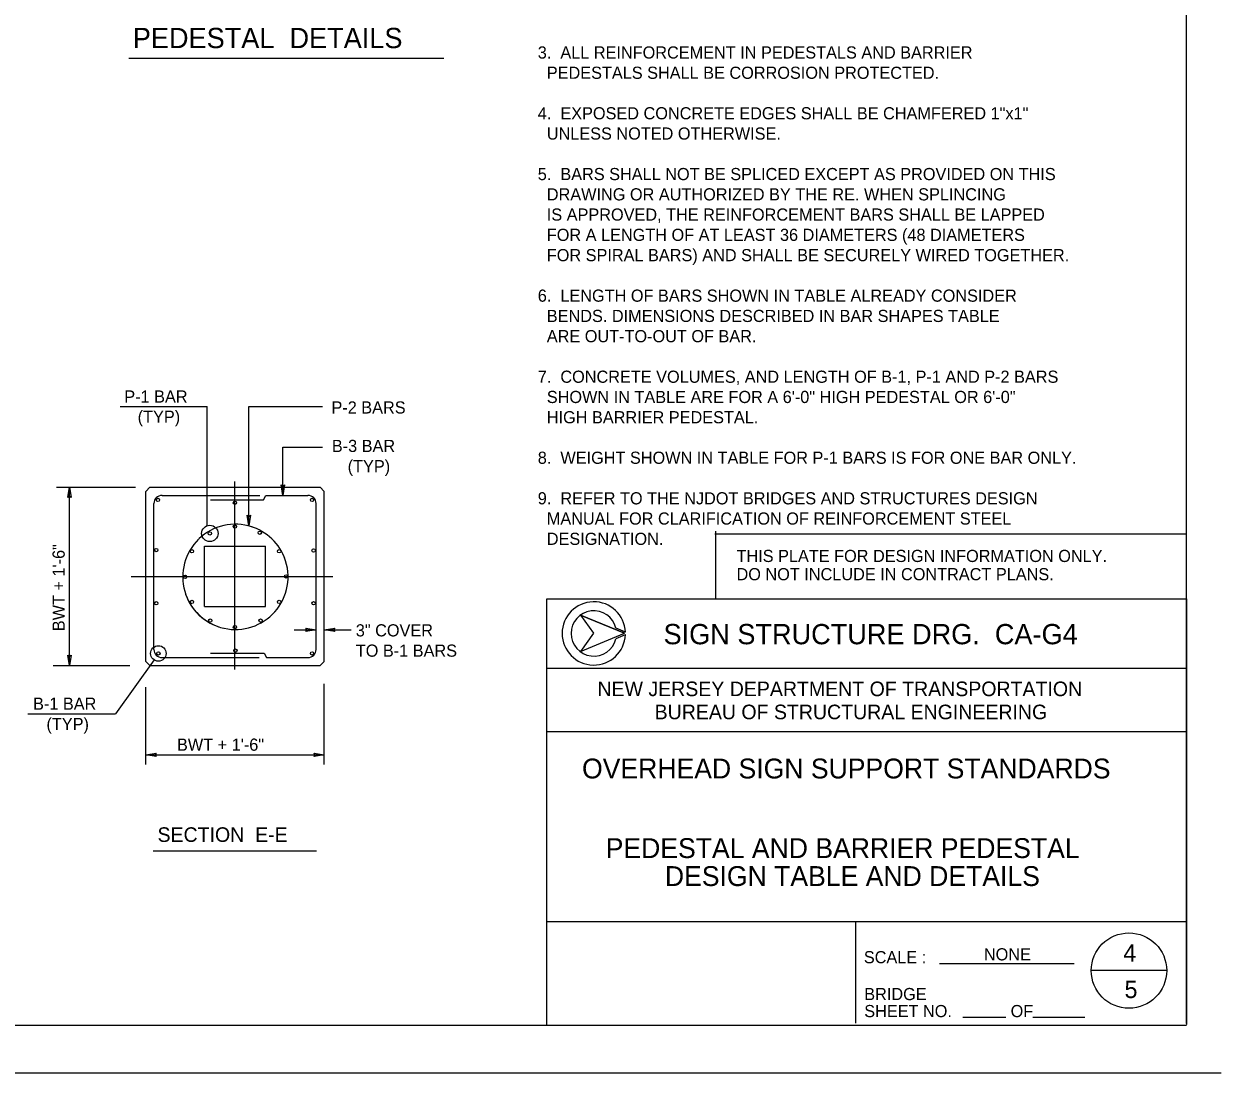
# Model space of a CAD drawing. Extents: x -3 to 26050223, y 0 to 12035012.
# Drawn here: x 44.29 to 68.89, y 0 to 21.57 of the extents above; entities that cross this region are included whole.
import ezdxf

# ---------------------------------------------------------------- set-up
doc = ezdxf.new("R2010")
doc.units = 0
for name, color, linetype in [('1', 7, 'Continuous'), ('2', 7, 'Continuous'), ('39', 7, 'Continuous'), ('51', 7, 'Continuous')]:
    doc.layers.add(name, color=color, linetype=linetype)

msp = doc.modelspace()

# ---------------------------------------------------------------- linework, layer by layer
at = {"layer": '1'}
for p, q in [((68.183, 1.017), (68.183, 42.342)), ((56.633, 9.042), (55.725, 9.417)), ((55.725, 9.417), (56.633, 9.042)), ((56.633, 9.042), (55.725, 9.417)), ((55.725, 9.417), (55.992, 9.042)), ((56.633, 9.042), (55.725, 9.417)), ((55.725, 9.417), (55.992, 9.042)), ((56.458, 9.15), (56.45, 9.15)), ((56.65, 9.067), (56.458, 9.15)), ((55.992, 9.042), (55.725, 8.667)), ((55.725, 8.667), (56.633, 9.042)), ((55.992, 9.042), (55.725, 8.667)), ((55.725, 8.667), (56.633, 9.042)), ((56.458, 8.933), (56.65, 9.017)), ((46.941, 4.57), (50.3, 4.57)), ((63.583, 1.15), (64.467, 1.15)), ((65.025, 1.15), (66.092, 1.15)), ((3.6, 0.983), (68.183, 0.983)), ((68.892, 0), (0, 0))]:
    msp.add_line(p, q, dxfattribs=at)
for radius, start, end in [(0.65, 2.2139, 357.7861), (0.467, 13.6941, 346.3059)]:
    msp.add_arc((55.999, 9.04), radius, start, end, dxfattribs=at)
at = {"layer": '39'}
for p, q in [((46.442, 20.865), (52.917, 20.865)), ((46.266, 13.703), (48.05, 13.703)), ((48.05, 11.253), (48.05, 13.703)), ((48.908, 11.253), (48.908, 13.703)), ((48.908, 13.703), (50.425, 13.703)), ((49.608, 11.878), (49.608, 12.87)), ((49.608, 12.87), (50.425, 12.87)), ((48.625, 8.295), (48.625, 12.161)), ((44.958, 12.045), (46.583, 12.045)), ((45.225, 8.378), (45.225, 12.045)), ((46.791, 11.961), (46.875, 12.045)), ((46.791, 8.461), (46.791, 11.961)), ((46.875, 12.045), (50.375, 12.045)), ((47.125, 11.878), (49.133, 11.878)), ((49.208, 11.786), (49.258, 11.878)), ((49.258, 11.878), (50.125, 11.878)), ((50.458, 11.961), (50.375, 12.045)), ((50.458, 8.461), (50.458, 11.961)), ((46.958, 8.711), (46.958, 11.711)), ((48.125, 11.786), (49.208, 11.786)), ((50.291, 8.711), (50.291, 11.711)), ((48.941, 11.245), (48.975, 11.236)), ((58.49, 11.086), (68.165, 11.086)), ((58.508, 9.75), (58.508, 11.142)), ((48, 10.836), (49.25, 10.836)), ((48, 9.595), (48, 10.836)), ((49.25, 9.595), (49.25, 10.836)), ((46.491, 10.211), (50.633, 10.211)), ((55.033, 1), (55.033, 9.75)), ((55.033, 9.75), (68.183, 9.75)), ((68.183, 9.75), (68.183, 1)), ((48, 9.595), (49.25, 9.595)), ((56.633, 9.042), (55.725, 9.417)), ((55.725, 9.417), (55.992, 9.042)), ((49.841, 9.111), (50.291, 9.111)), ((50.458, 9.111), (51.016, 9.111)), ((55.992, 9.042), (55.725, 8.667)), ((55.725, 8.667), (56.633, 9.042)), ((48.125, 8.636), (49.225, 8.636)), ((49.225, 8.636), (49.275, 8.545)), ((44.891, 8.378), (46.466, 8.378)), ((46.966, 8.495), (46.166, 7.386)), ((46.791, 8.461), (46.875, 8.378)), ((46.875, 8.378), (50.375, 8.378)), ((47.125, 8.545), (49.125, 8.545)), ((49.275, 8.545), (50.125, 8.545)), ((50.458, 8.461), (50.375, 8.378)), ((55.033, 8.325), (68.183, 8.325)), ((46.791, 6.345), (46.791, 7.936)), ((50.458, 6.345), (50.458, 8.003)), ((44.366, 7.386), (46.166, 7.386)), ((55.033, 7.025), (68.183, 7.025)), ((46.791, 6.545), (50.458, 6.545)), ((55.033, 3.117), (68.183, 3.117)), ((61.383, 3.117), (68.183, 3.117)), ((61.383, 1.025), (61.383, 3.117)), ((61.383, 1.025), (61.383, 3.117)), ((63.108, 2.25), (65.875, 2.25)), ((67.775, 2.108), (66.225, 2.108))]:
    msp.add_line(p, q, dxfattribs=at)
for points in [[(49.608, 12.07), (49.641, 12.095), (49.608, 11.878), (49.575, 12.095)], [(45.225, 11.853), (45.191, 11.836), (45.225, 12.045), (45.258, 11.836)], [(48.908, 11.445), (48.941, 11.47), (48.908, 11.253), (48.875, 11.47)], [(50.1, 9.111), (50.083, 9.145), (50.291, 9.111), (50.083, 9.078)], [(50.65, 9.111), (50.675, 9.078), (50.458, 9.111), (50.675, 9.145)], [(45.225, 8.57), (45.258, 8.595), (45.225, 8.378), (45.191, 8.595)], [(46.983, 6.545), (47.008, 6.511), (46.791, 6.545), (47.008, 6.578)], [(50.266, 6.545), (50.25, 6.578), (50.458, 6.545), (50.25, 6.511)]]:
    msp.add_lwpolyline(points, close=True, dxfattribs=at)
for centre, radius in [((47.041, 11.786), 0.0344), ((50.208, 11.786), 0.0344), ((48.625, 11.728), 0.0344), ((48.108, 11.095), 0.168), ((48.108, 11.095), 0.0344), ((48.625, 11.236), 0.0344), ((49.133, 11.111), 0.0344), ((47.008, 10.753), 0.0344), ((47.741, 10.728), 0.0344), ((49.533, 10.728), 0.0344), ((50.241, 10.745), 0.0344), ((47.6, 10.203), 0.0344), ((49.675, 10.211), 0.0344), ((47.008, 9.661), 0.0344), ((47.741, 9.686), 0.0344), ((49.533, 9.686), 0.0344), ((50.241, 9.661), 0.0344), ((48.116, 9.303), 0.0344), ((48.625, 9.17), 0.0344), ((49.15, 9.303), 0.0344), ((47.05, 8.628), 0.159), ((47.05, 8.628), 0.0344), ((48.633, 8.686), 0.0344), ((50.208, 8.628), 0.0344), ((66.999, 2.107), 0.775)]:
    msp.add_circle(centre, radius, dxfattribs=at)
for centre, radius, start, end in [((47.125, 11.711), 0.167, 90, 180), ((50.125, 11.711), 0.167, 0, 90), ((48.633, 10.203), 1.083, 71.834, 133.8188), ((48.633, 10.203), 1.083, 71.834, 133.8188), ((48.633, 10.203), 1.083, 18.8491, 73.3856), ((48.633, 10.203), 1.083, 18.8491, 73.3856), ((48.633, 10.203), 1.083, 134.3013, 257.417), ((48.633, 10.203), 1.083, 134.3013, 257.417), ((48.633, 10.203), 1.083, 318.2583, 21.5713), ((48.633, 10.203), 1.083, 318.2583, 21.5713), ((48.633, 10.203), 1.083, 199.2693, 251.1509), ((48.633, 10.203), 1.083, 257.7537, 318.5323), ((48.633, 10.203), 1.083, 257.7537, 318.5323), ((47.125, 8.711), 0.167, 180, 270), ((50.125, 8.711), 0.167, 270, 0)]:
    msp.add_arc(centre, radius, start, end, dxfattribs=at)

# ---------------------------------------------------------------- texts
at = {"layer": '2'}
for s, height, p in [('P-1 BAR', 0.25, (46.35, 13.786)), ('P-2 BARS', 0.25, (50.608, 13.561)), ('(TYP)', 0.25, (46.625, 13.37)), ('B-3 BAR', 0.25, (50.616, 12.77)), ('(TYP)', 0.25, (50.941, 12.353)), ('THIS PLATE FOR DESIGN INFORMATION ONLY.', 0.25, (58.933, 10.508)), ('DO NOT INCLUDE IN CONTRACT PLANS.', 0.25, (58.933, 10.133)), ('3" COVER', 0.25, (51.108, 8.978)), ('TO B-1 BARS', 0.25, (51.108, 8.561)), ('B-1 BAR', 0.25, (44.475, 7.47)), ('(TYP)', 0.25, (44.75, 7.053)), ('BWT + 1\'-6"', 0.25, (47.433, 6.628)), ('OVERHEAD SIGN SUPPORT STANDARDS', 0.40835, (55.758, 6.058)), ('PEDESTAL AND BARRIER PEDESTAL ', 0.40835, (56.244, 4.421)), ('DESIGN TABLE AND DETAILS', 0.40835, (57.461, 3.846))]:
    msp.add_text(s, height=height, dxfattribs=at).set_placement(p)
msp.add_text('BWT + 1\'-6"', height=0.25, rotation=90, dxfattribs=at).set_placement((45.125, 9.086))
at = {"layer": '39'}
for s, height, p in [('PEDESTAL  DETAILS', 0.41665, (46.525, 21.074)), ('3.  ALL REINFORCEMENT IN PEDESTALS AND BARRIER ', 0.25, (54.848, 20.86)), ('  PEDESTALS SHALL BE CORROSION PROTECTED.', 0.25, (54.848, 20.443)), ('4.  EXPOSED CONCRETE EDGES SHALL BE CHAMFERED 1"x1" ', 0.25, (54.848, 19.61)), ('  UNLESS NOTED OTHERWISE.', 0.25, (54.848, 19.193)), ('5.  BARS SHALL NOT BE SPLICED EXCEPT AS PROVIDED ON THIS', 0.25, (54.848, 18.36)), ('  DRAWING OR AUTHORIZED BY THE RE. WHEN SPLINCING ', 0.25, (54.848, 17.943)), ('  IS APPROVED, THE REINFORCEMENT BARS SHALL BE LAPPED ', 0.25, (54.848, 17.527)), ('  FOR A LENGTH OF AT LEAST 36 DIAMETERS (48 DIAMETERS  ', 0.25, (54.848, 17.11)), ('  FOR SPIRAL BARS) AND SHALL BE SECURELY WIRED TOGETHER.', 0.25, (54.848, 16.693)), ('6.  LENGTH OF BARS SHOWN IN TABLE ALREADY CONSIDER ', 0.25, (54.848, 15.86)), ('  BENDS. DIMENSIONS DESCRIBED IN BAR SHAPES TABLE ', 0.25, (54.848, 15.443)), ('  ARE OUT-TO-OUT OF BAR.', 0.25, (54.848, 15.027)), ('7.  CONCRETE VOLUMES, AND LENGTH OF B-1, P-1 AND P-2 BARS ', 0.25, (54.848, 14.193)), ('  SHOWN IN TABLE ARE FOR A 6\'-0" HIGH PEDESTAL OR 6\'-0" ', 0.25, (54.848, 13.777)), ('  HIGH BARRIER PEDESTAL.', 0.25, (54.848, 13.36)), ('8.  WEIGHT SHOWN IN TABLE FOR P-1 BARS IS FOR ONE BAR ONLY.', 0.25, (54.848, 12.527)), ('9.  REFER TO THE NJDOT BRIDGES AND STRUCTURES DESIGN ', 0.25, (54.848, 11.693)), ('  MANUAL FOR CLARIFICATION OF REINFORCEMENT STEEL ', 0.25, (54.848, 11.277)), ('  DESIGNATION.', 0.25, (54.848, 10.86)), ('SIGN STRUCTURE DRG.  CA-G4', 0.41665, (57.433, 8.817)), ('NEW JERSEY DEPARTMENT OF TRANSPORTATION', 0.29995, (56.075, 7.75)), ('BUREAU OF STRUCTURAL ENGINEERING', 0.3, (57.25, 7.275)), ('SECTION  E-E', 0.3, (47.033, 4.753)), ('SCALE :', 0.25, (61.55, 2.258)), ('SCALE :', 0.25, (61.55, 2.258)), ('SCALE :', 0.25, (61.55, 2.258)), ('NONE', 0.25, (64.017, 2.317)), ('BRIDGE', 0.25, (61.558, 1.5)), ('BRIDGE', 0.25, (61.558, 1.5)), ('BRIDGE', 0.25, (61.558, 1.5)), ('SHEET NO.', 0.25, (61.558, 1.15)), ('SHEET NO.', 0.25, (61.558, 1.15)), ('SHEET NO.', 0.25, (61.558, 1.15)), ('OF', 0.25, (64.567, 1.15))]:
    msp.add_text(s, height=height, dxfattribs=at).set_placement(p)
at = {"layer": '51'}
for s, p in [('4', (66.883, 2.292)), ('5', (66.908, 1.542))]:
    msp.add_text(s, height=0.358, dxfattribs=at).set_placement(p)

doc.saveas('drawing.dxf')
